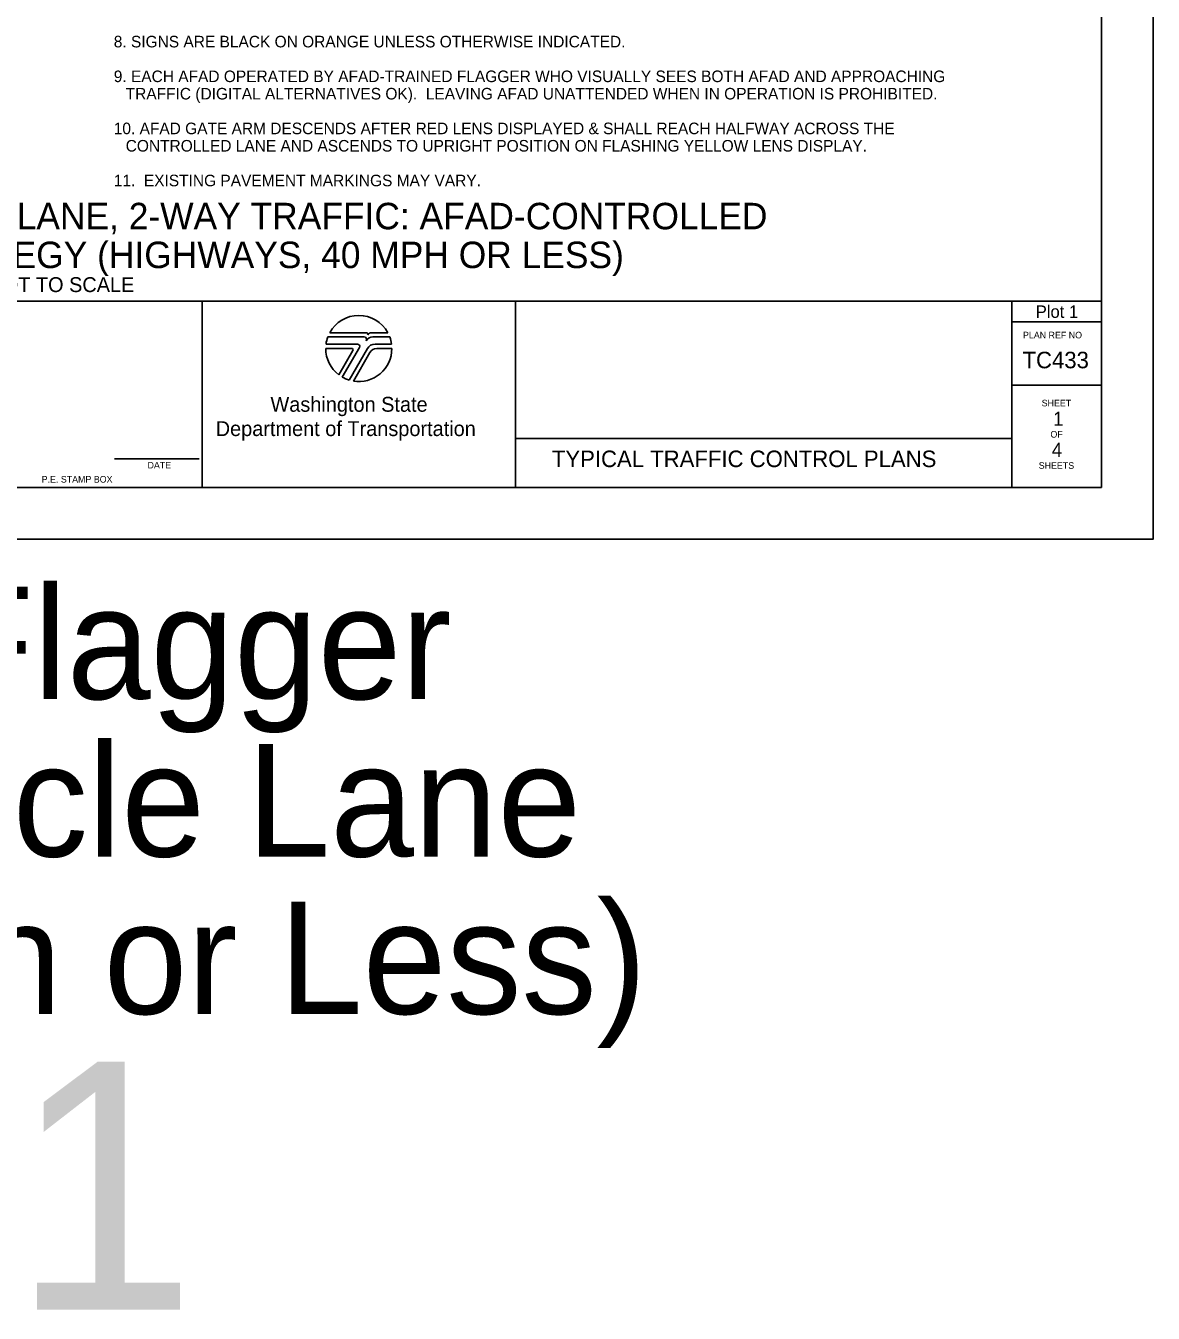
# Model space of a CAD drawing. Extents: x 99999.1 to 100095.7, y 99995 to 100010.7.
# Drawn here: x 100009.24 to 100016.06, y 99995.01 to 100002.79 of the extents above; entities that cross this region are included whole.
import ezdxf

# ---------------------------------------------------------------- set-up
doc = ezdxf.new("R2010")
doc.units = 0
for name, color, linetype in [('SH_DE_DetailHeading1Text', 7, 'Continuous'), ('SH_GI_GeneralNotesBodyText', 7, 'Continuous'), ('SH_GI_PlotLimits', 7, 'Continuous'), ('SH_GI_SheetBorder', 7, 'Continuous'), ('SH_GI_SheetLocationText', 7, 'Continuous'), ('SH_GI_SheetTextInCells', 7, 'Continuous'), ('SH_GI_TitleBlockText', 7, 'Continuous'), ('SH_GI_WSDOTLogo', 7, 'Continuous')]:
    doc.layers.add(name, color=color, linetype=linetype)

msp = doc.modelspace()

# ---------------------------------------------------------------- linework, layer by layer
at = {"layer": 'SH_GI_PlotLimits'}
msp.add_lwpolyline([(99999.0625, 99999.6875), (100016.0625, 99999.6875), (100016.0625, 100010.6875), (99999.0625, 100010.6875)], close=True, dxfattribs=at)
at = {"layer": 'SH_GI_SheetBorder'}
for p, q in [((100015.75, 100010.375), (100015.75, 100000)), ((100000, 100001.1259), (100015.75, 100001.1259)), ((100010.3089, 100001.1259), (100010.3089, 100000)), ((100012.2055, 100001.1259), (100012.2055, 100000)), ((100015.2079, 100001.1259), (100015.2079, 100000)), ((100015.2079, 100001.0008), (100015.75, 100001.0008)), ((100015.2079, 100000.6176), (100015.75, 100000.6176)), ((100012.2055, 100000.2955), (100015.2079, 100000.2955)), ((100009.7797, 100000.1733), (100010.2914, 100000.1733)), ((100000, 100000), (100015.75, 100000))]:
    msp.add_line(p, q, dxfattribs=at)
at = {"layer": 'SH_GI_WSDOTLogo'}
for p, q in [((100011.2894, 100000.9094), (100011.0697, 100000.9094)), ((100011.303, 100000.9354), (100011.0815, 100000.9354)), ((100011.433, 100000.9354), (100011.3351, 100000.9354)), ((100011.343, 100000.9094), (100011.3429, 100000.9094)), ((100011.4448, 100000.9094), (100011.343, 100000.9094)), ((100011.0572, 100000.84), (100011.2148, 100000.84)), ((100011.059, 100000.8661), (100011.2496, 100000.8661)), ((100011.222, 100000.8277), (100011.1364, 100000.6807)), ((100011.261, 100000.8464), (100011.1567, 100000.6672)), ((100011.1989, 100000.6487), (100011.3089, 100000.839)), ((100011.3558, 100000.8661), (100011.4555, 100000.8661)), ((100011.3655, 100000.8394), (100011.4572, 100000.8394)), ((100011.2244, 100000.6428), (100011.3242, 100000.8156))]:
    msp.add_line(p, q, dxfattribs=at)
for centre, radius, start, end in [((100011.2572, 100000.84), 0.2, 28.47865, 151.53204), ((100011.2572, 100000.84), 0.2, 159.69598, 172.50569), ((100011.2894, 100000.8946), 0.0148, 327.8418, 89.99855), ((100011.3429, 100000.861), 0.0484, 89.99529, 147.82376), ((100011.303, 100000.9263), 0.00903, 329.87418, 90.00328), ((100011.3352, 100000.9066), 0.0287, 90.00721, 148.16763), ((100011.2572, 100000.84), 0.2, 7.49431, 20.29406), ((100011.2572, 100000.84), 0.2, 179.99864, 232.84327), ((100011.2149, 100000.8318), 0.0082, 329.74356, 90), ((100011.2572, 100000.84), 0.2, 260.54554, 359.80857), ((100011.2497, 100000.853), 0.0131, 329.76834, 90), ((100011.3558, 100000.8119), 0.0542, 90, 149.99738), ((100011.3654, 100000.7918), 0.0476, 90, 150.05432), ((100011.2572, 100000.84), 0.2, 239.79292, 253.0448)]:
    msp.add_arc(centre, radius, start, end, dxfattribs=at)

# ---------------------------------------------------------------- texts
at = {"layer": 'SH_DE_DetailHeading1Text'}
for s, height, p in [('PILOT CAR OPERATION FOR ALTERNATING 1-LANE, 2-WAY TRAFFIC: AFAD-CONTROLLED', 0.16, (100004.4207, 100001.5606)), ('SHARED BIKE-VEHICLE LANE STRATEGY (HIGHWAYS, 40 MPH OR LESS)', 0.16, (100005.3584, 100001.3259)), ('NOT TO SCALE', 0.09, (100009.0168, 100001.1809))]:
    msp.add_text(s, height=height, rotation=360, dxfattribs=at).set_placement(p)
at = {"layer": 'SH_GI_GeneralNotesBodyText'}
for s, p in [('8. SIGNS ARE BLACK ON ORANGE UNLESS OTHERWISE INDICATED.', (100009.7751, 100002.6606)), ('9. EACH AFAD OPERATED BY AFAD-TRAINED FLAGGER WHO VISUALLY SEES BOTH AFAD AND APPROACHING ', (100009.7751, 100002.4506)), ('TRAFFIC (DIGITAL ALTERNATIVES OK).  LEAVING AFAD UNATTENDED WHEN IN OPERATION IS PROHIBITED.', (100009.8473, 100002.3456)), ('10. AFAD GATE ARM DESCENDS AFTER RED LENS DISPLAYED & SHALL REACH HALFWAY ACROSS THE ', (100009.7751, 100002.1356)), ('CONTROLLED LANE AND ASCENDS TO UPRIGHT POSITION ON FLASHING YELLOW LENS DISPLAY.', (100009.8473, 100002.0306)), ('11.  EXISTING PAVEMENT MARKINGS MAY VARY.', (100009.7751, 100001.8206))]:
    msp.add_text(s, height=0.07, rotation=360, dxfattribs=at).set_placement(p)
at = {"layer": 'SH_GI_SheetBorder'}
msp.add_text('PLAN REF NO', height=0.040032, dxfattribs=at).set_placement((100015.2747, 100000.9008))
at = {"layer": 'SH_GI_SheetLocationText'}
for s, height, p in [('Plot 1', 0.075, (100015.3518, 100001.025)), ('Pilot Car Op: Flagger', 0.68, (100003.2766, 99998.7191)), ('Shared Bike-Vehicle Lane', 0.68, (100002.0877, 99997.7671)), ('(Highways, 40 mph or Less)', 0.68, (100001.6785, 99996.8151)), ('Plot 1', 1.5, (100005.1448, 99995.0267))]:
    msp.add_text(s, height=height, dxfattribs=at).set_placement(p)
at = {"layer": 'SH_GI_SheetTextInCells'}
for s, height, p in [('Washington State', 0.090072, (100010.7229, 100000.4571)), ('SHEET', 0.04003, (100015.3877, 100000.4896)), ('Department of Transportation', 0.090072, (100010.3916, 100000.3101)), ('OF', 0.04003, (100015.4406, 100000.3008)), ('DATE', 0.04003, (100009.9794, 100000.1141)), ('SHEETS', 0.04003, (100015.3698, 100000.112)), ('P.E. STAMP BOX', 0.040032, (100009.339, 100000.0286))]:
    msp.add_text(s, height=height, dxfattribs=at).set_placement(p)
at = {"layer": 'SH_GI_TitleBlockText'}
for s, height, p in [('TC433', 0.1, (100015.2718, 100000.72)), ('1', 0.085, (100015.4566, 100000.3723)), ('TYPICAL TRAFFIC CONTROL PLANS', 0.1, (100012.4251, 100000.1224)), ('4', 0.085, (100015.4485, 100000.1843))]:
    msp.add_text(s, height=height, dxfattribs=at).set_placement(p)

doc.saveas('drawing.dxf')
